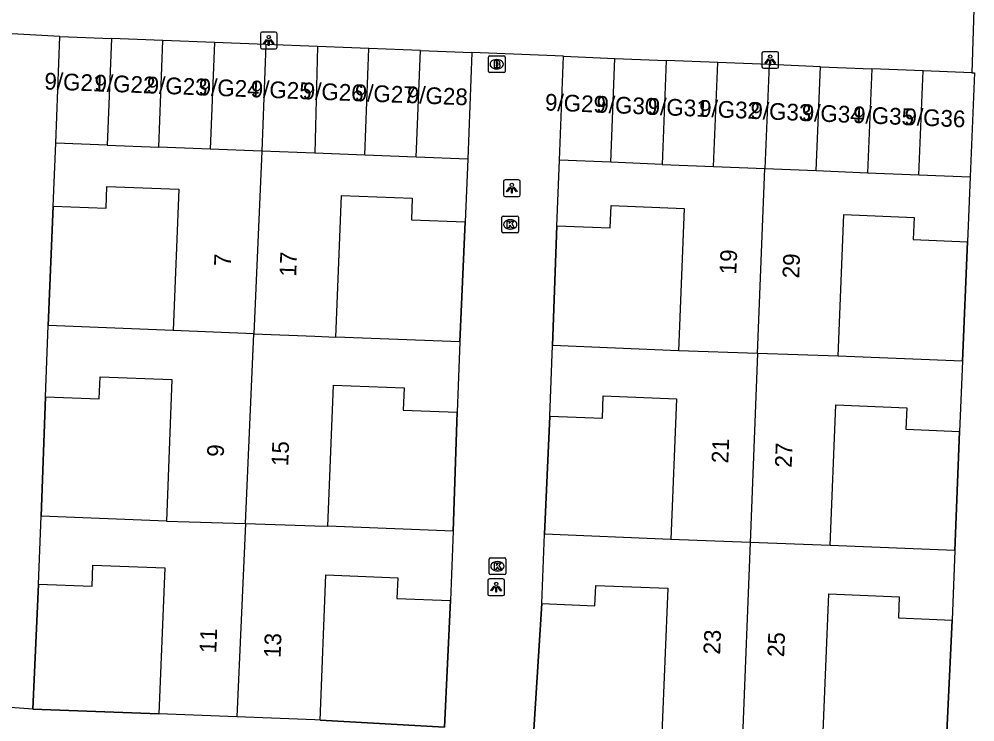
# Model space of a CAD drawing. Extents: x 160787 to 161428, y 386828 to 387483.
# Drawn here: x 160982.3 to 161039.5, y 387304.5 to 387346.5 of the extents above; entities that cross this region are included whole.
import ezdxf

# ---------------------------------------------------------------- set-up
doc = ezdxf.new("R2010")
doc.units = 0
for name, color, linetype in [('IMGEO_Brandkraan', 7, 'Continuous'), ('IMGEO_Kolk', 7, 'Continuous'), ('IMGEO_Lichtpunt', 7, 'Continuous'), ('IMGEO_Muur', 7, 'Continuous'), ('IMGEO_Pand', 7, 'Continuous'), ('IMGEO_Pand_nummerreeks', 7, 'Continuous'), ('IMGEO_Rijbaan_lokaal_open', 7, 'Continuous'), ('IMGEO_Voetpad_open', 7, 'Continuous')]:
    doc.layers.add(name, color=color, linetype=linetype)

msp = doc.modelspace()

# ---------------------------------------------------------------- linework, layer by layer
at = {"layer": 'IMGEO_Brandkraan'}
for p, q in [((161010.378, 387343.371), (161010.378, 387344.223)), ((161010.453, 387344.297), (161011.305, 387344.297)), ((161011.379, 387344.223), (161011.379, 387343.371)), ((161010.866, 387344.077), (161010.891, 387344.077)), ((161011.305, 387343.297), (161010.453, 387343.297)), ((161010.889, 387343.517), (161010.864, 387343.517))]:
    msp.add_line(p, q, dxfattribs=at)
for points in [[(161010.378, 387343.371), (161010.378, 387344.223)], [(161010.453, 387344.297), (161011.305, 387344.297)], [(161011.379, 387344.223), (161011.379, 387343.371)], [(161010.726, 387343.997), (161010.726, 387343.597), (161010.939, 387343.597)], [(161010.957, 387343.997), (161010.726, 387343.997)], [(161010.905, 387343.916), (161010.851, 387343.916), (161010.851, 387343.84)], [(161010.851, 387343.84), (161010.904, 387343.84)], [(161010.913, 387343.764), (161010.851, 387343.764), (161010.851, 387343.683)], [(161010.851, 387343.683), (161010.913, 387343.683)], [(161011.305, 387343.297), (161010.453, 387343.297)]]:
    msp.add_lwpolyline(points, dxfattribs=at)
for centre, radius, start, end in [((161010.455, 387344.221), 0.0765, 91.552, 178.448), ((161010.455, 387344.221), 0.0765, 91.552, 178.448), ((161011.303, 387344.221), 0.0765, 1.552, 88.448), ((161011.303, 387344.221), 0.0765, 1.552, 88.448), ((161010.906, 387343.878), 0.0379, 267.8285, 90.9355), ((161010.914, 387343.723), 0.0404, 269.8759, 90.5077), ((161010.945, 387343.848), 0.251, 268.6676, 293.5347), ((161010.961, 387343.852), 0.145, 59.4692, 91.5367), ((161010.986, 387343.899), 0.0922, 285.5137, 58.1501), ((161010.991, 387343.707), 0.105, 301.3115, 78.989), ((161010.455, 387343.373), 0.0765, 181.552, 268.448), ((161010.455, 387343.373), 0.0765, 181.552, 268.448), ((161011.303, 387343.373), 0.0765, 271.552, 358.448), ((161011.303, 387343.373), 0.0765, 271.552, 358.448)]:
    msp.add_arc(centre, radius, start, end, dxfattribs=at)
for centre, major_axis, ratio, start_param, end_param in [((161010.865, 387343.797), (-0.387, 0.002), 0.722429, 4.712389, 7.853982), ((161010.89, 387343.797), (-0.39, 0.002), 0.717154, 1.570796, 4.712389)]:
    msp.add_ellipse(centre, major_axis=major_axis, ratio=ratio, start_param=start_param, end_param=end_param, dxfattribs=at)
at = {"layer": 'IMGEO_Kolk'}
for p, q in [((161011.185, 387333.79), (161011.185, 387334.642)), ((161011.26, 387334.716), (161012.112, 387334.716)), ((161011.673, 387334.496), (161011.698, 387334.496)), ((161012.186, 387334.642), (161012.186, 387333.79)), ((161011.696, 387333.936), (161011.671, 387333.936)), ((161012.112, 387333.716), (161011.26, 387333.716)), ((161010.423, 387313.34), (161010.423, 387314.192)), ((161010.498, 387314.266), (161011.35, 387314.266)), ((161010.911, 387314.046), (161010.936, 387314.046)), ((161011.424, 387314.192), (161011.424, 387313.34)), ((161011.35, 387313.266), (161010.498, 387313.266)), ((161010.934, 387313.486), (161010.909, 387313.486))]:
    msp.add_line(p, q, dxfattribs=at)
for points in [[(161011.185, 387333.79), (161011.185, 387334.642)], [(161011.26, 387334.716), (161012.112, 387334.716)], [(161011.506, 387334.416), (161011.629, 387334.416), (161011.629, 387334.265), (161011.759, 387334.416), (161011.923, 387334.416), (161011.777, 387334.265), (161011.93, 387334.016), (161011.778, 387334.016), (161011.693, 387334.18), (161011.629, 387334.113), (161011.629, 387334.016), (161011.506, 387334.016), (161011.506, 387334.416)], [(161012.186, 387334.642), (161012.186, 387333.79)], [(161012.112, 387333.716), (161011.26, 387333.716)], [(161010.423, 387313.34), (161010.423, 387314.192)], [(161010.498, 387314.266), (161011.35, 387314.266)], [(161010.744, 387313.966), (161010.867, 387313.966), (161010.867, 387313.815), (161010.997, 387313.966), (161011.161, 387313.966), (161011.015, 387313.815), (161011.168, 387313.566), (161011.016, 387313.566), (161010.931, 387313.73), (161010.867, 387313.663), (161010.867, 387313.566), (161010.744, 387313.566), (161010.744, 387313.966)], [(161011.424, 387314.192), (161011.424, 387313.34)], [(161011.35, 387313.266), (161010.498, 387313.266)]]:
    msp.add_lwpolyline(points, dxfattribs=at)
for centre, start, end in [((161011.262, 387334.64), 91.552, 178.448), ((161011.262, 387334.64), 91.552, 178.448), ((161012.11, 387334.64), 1.552, 88.448), ((161012.11, 387334.64), 1.552, 88.448), ((161011.262, 387333.792), 181.552, 268.448), ((161011.262, 387333.792), 181.552, 268.448), ((161012.11, 387333.792), 271.552, 358.448), ((161012.11, 387333.792), 271.552, 358.448), ((161010.5, 387314.19), 91.552, 178.448), ((161010.5, 387314.19), 91.552, 178.448), ((161011.348, 387314.19), 1.552, 88.448), ((161011.348, 387314.19), 1.552, 88.448), ((161010.5, 387313.342), 181.552, 268.448), ((161010.5, 387313.342), 181.552, 268.448), ((161011.348, 387313.342), 271.552, 358.448), ((161011.348, 387313.342), 271.552, 358.448)]:
    msp.add_arc(centre, 0.0765, start, end, dxfattribs=at)
for centre, major_axis, ratio, start_param, end_param in [((161011.672, 387334.216), (-0.387, 0.002), 0.722429, 4.712389, 7.853982), ((161011.697, 387334.216), (-0.39, 0.002), 0.717154, 1.570796, 4.712389), ((161010.91, 387313.766), (-0.387, 0.002), 0.722429, 4.712389, 7.853982), ((161010.935, 387313.766), (-0.39, 0.002), 0.717154, 1.570796, 4.712389)]:
    msp.add_ellipse(centre, major_axis=major_axis, ratio=ratio, start_param=start_param, end_param=end_param, dxfattribs=at)
at = {"layer": 'IMGEO_Lichtpunt'}
for p, q in [((160996.743, 387345.622), (160996.743, 387344.815)), ((160996.743, 387345.622), (160996.743, 387344.815)), ((160997.645, 387345.717), (160996.837, 387345.717)), ((160997.645, 387345.717), (160996.837, 387345.717)), ((160997.739, 387344.815), (160997.739, 387345.622)), ((160997.739, 387344.815), (160997.739, 387345.622)), ((160996.837, 387344.721), (160997.645, 387344.721)), ((160996.837, 387344.721), (160997.645, 387344.721)), ((161026.739, 387344.454), (161026.739, 387343.647)), ((161026.739, 387344.454), (161026.739, 387343.647)), ((161027.641, 387344.549), (161026.833, 387344.549)), ((161027.641, 387344.549), (161026.833, 387344.549)), ((161027.735, 387343.647), (161027.735, 387344.454)), ((161027.735, 387343.647), (161027.735, 387344.454)), ((161026.833, 387343.553), (161027.641, 387343.553)), ((161026.833, 387343.553), (161027.641, 387343.553)), ((161011.284, 387336.783), (161011.284, 387335.976)), ((161011.284, 387336.783), (161011.284, 387335.976)), ((161012.186, 387336.878), (161011.378, 387336.878)), ((161012.186, 387336.878), (161011.378, 387336.878)), ((161012.28, 387335.976), (161012.28, 387336.783)), ((161012.28, 387335.976), (161012.28, 387336.783)), ((161011.378, 387335.882), (161012.186, 387335.882)), ((161011.378, 387335.882), (161012.186, 387335.882)), ((161010.348, 387312.914), (161010.348, 387312.107)), ((161010.348, 387312.914), (161010.348, 387312.107)), ((161011.25, 387313.009), (161010.442, 387313.009)), ((161011.25, 387313.009), (161010.442, 387313.009)), ((161011.344, 387312.107), (161011.344, 387312.914)), ((161011.344, 387312.107), (161011.344, 387312.914)), ((161010.442, 387312.013), (161011.25, 387312.013)), ((161010.442, 387312.013), (161011.25, 387312.013))]:
    msp.add_line(p, q, dxfattribs=at)
for points in [[(160997.117, 387345.286), (160997.156, 387345.258), (160996.968, 387344.996), (160996.93, 387345.023), (160997.117, 387345.286)], [(160997.329, 387345.258), (160997.367, 387345.285), (160997.554, 387345.023), (160997.515, 387344.995), (160997.329, 387345.258)], [(160997.219, 387345.238), (160997.266, 387345.238), (160997.266, 387344.916), (160997.219, 387344.916), (160997.219, 387345.238)], [(161027.113, 387344.118), (161027.152, 387344.09), (161026.964, 387343.828), (161026.926, 387343.855), (161027.113, 387344.118)], [(161027.325, 387344.09), (161027.363, 387344.117), (161027.55, 387343.855), (161027.511, 387343.827), (161027.325, 387344.09)], [(161027.215, 387344.07), (161027.262, 387344.07), (161027.262, 387343.748), (161027.215, 387343.748), (161027.215, 387344.07)], [(161011.658, 387336.447), (161011.697, 387336.419), (161011.509, 387336.157), (161011.471, 387336.184), (161011.658, 387336.447)], [(161011.76, 387336.399), (161011.807, 387336.399), (161011.807, 387336.077), (161011.76, 387336.077), (161011.76, 387336.399)], [(161011.87, 387336.419), (161011.908, 387336.446), (161012.095, 387336.184), (161012.056, 387336.156), (161011.87, 387336.419)], [(161010.722, 387312.578), (161010.761, 387312.55), (161010.573, 387312.288), (161010.535, 387312.315), (161010.722, 387312.578)], [(161010.824, 387312.53), (161010.871, 387312.53), (161010.871, 387312.208), (161010.824, 387312.208), (161010.824, 387312.53)], [(161010.934, 387312.55), (161010.972, 387312.577), (161011.159, 387312.315), (161011.12, 387312.287), (161010.934, 387312.55)]]:
    msp.add_lwpolyline(points, dxfattribs=at)
for centre in [(160997.242, 387345.42), (161027.238, 387344.252), (161011.783, 387336.581), (161010.847, 387312.712)]:
    msp.add_circle(centre, 0.0994, dxfattribs=at)
for centre, start, end in [((160996.837, 387345.622), 90, 180), ((160996.837, 387345.622), 90, 180), ((160997.645, 387345.622), 0, 90), ((160997.645, 387345.622), 0, 90), ((160996.837, 387344.815), 180, 270), ((160996.837, 387344.815), 180, 270), ((160997.645, 387344.815), 270, 0), ((160997.645, 387344.815), 270, 360), ((161026.833, 387344.454), 90, 180), ((161026.833, 387344.454), 90, 180), ((161027.641, 387344.454), 0, 90), ((161027.641, 387344.454), 0, 90), ((161026.833, 387343.647), 180, 270), ((161026.833, 387343.647), 180, 270), ((161027.641, 387343.647), 270, 0), ((161027.641, 387343.647), 270, 360), ((161011.378, 387336.783), 90, 180), ((161011.378, 387336.783), 90, 180), ((161012.186, 387336.783), 0, 90), ((161012.186, 387336.783), 0, 90), ((161011.378, 387335.976), 180, 270), ((161011.378, 387335.976), 180, 270), ((161012.186, 387335.976), 270, 0), ((161012.186, 387335.976), 270, 360), ((161010.442, 387312.914), 90, 180), ((161010.442, 387312.914), 90, 180), ((161011.25, 387312.914), 0, 90), ((161011.25, 387312.914), 0, 90), ((161010.442, 387312.107), 180, 270), ((161010.442, 387312.107), 180, 270), ((161011.25, 387312.107), 270, 0), ((161011.25, 387312.107), 270, 360)]:
    msp.add_arc(centre, 0.0946, start, end, dxfattribs=at)
at = {"layer": 'IMGEO_Muur'}
for points in [[(160984.36, 387335.313), (160984.055, 387328.17)], [(161008.672, 387327.188), (161008.998, 387334.368)], [(161014.47, 387334.14), (161014.22, 387326.967)], [(161038.733, 387326.037), (161039.04, 387333.18)], [(160983.887, 387323.905), (160983.626, 387316.762)], [(161008.28, 387315.875), (161008.507, 387322.987)], [(161014.049, 387322.75), (161013.745, 387315.68)], [(161038.281, 387314.709), (161038.563, 387321.838)], [(160983.467, 387312.699), (160983.144, 387305.21), (160990.678, 387304.943)], [(161000.326, 387304.564), (161007.761, 387304.145), (161008.117, 387311.71)], [(161013.577, 387311.533), (161013.104, 387303.992)], [(161037.77, 387302.999), (161038.112, 387310.547)]]:
    msp.add_lwpolyline(points, dxfattribs=at)
at = {"layer": 'IMGEO_Pand'}
for points in [[(160984.508, 387339.08), (160984.758, 387345.458)], [(160984.758, 387345.458), (160987.838, 387345.337)], [(160987.838, 387345.337), (160987.587, 387338.959)], [(160990.918, 387345.216), (160987.838, 387345.337)], [(160990.667, 387338.837), (160990.918, 387345.216)], [(160993.997, 387345.095), (160990.918, 387345.216)], [(160993.997, 387345.095), (160993.747, 387338.716)], [(160997.077, 387344.975), (160993.997, 387345.095)], [(160997.077, 387344.975), (160996.826, 387338.595)], [(161000.157, 387344.854), (160997.077, 387344.975)], [(161000.157, 387344.854), (161000, 387338.47)], [(161003.236, 387344.733), (161000.157, 387344.854)], [(161002.986, 387338.352), (161003.236, 387344.733)], [(161006.316, 387344.612), (161003.236, 387344.733)], [(161006.066, 387338.231), (161006.316, 387344.612)], [(161006.316, 387344.612), (161009.396, 387344.491)], [(161009.396, 387344.491), (161009.145, 387338.11)], [(161014.629, 387338.054), (161014.881, 387344.271)], [(161014.881, 387344.271), (161017.952, 387344.147)], [(161017.7, 387337.93), (161017.952, 387344.147)], [(161017.952, 387344.147), (161021.023, 387344.022)], [(161021.023, 387344.022), (161020.771, 387337.805)], [(161024.094, 387343.898), (161021.023, 387344.022)], [(161023.842, 387337.681), (161024.094, 387343.898)], [(161027.165, 387343.773), (161024.094, 387343.898)], [(161027.165, 387343.773), (161026.913, 387337.556)], [(161030.236, 387343.648), (161027.165, 387343.773)], [(161029.984, 387337.432), (161030.236, 387343.648)], [(161030.236, 387343.648), (161033.307, 387343.524)], [(161033.307, 387343.524), (161033.055, 387337.308)], [(161036.378, 387343.4), (161033.307, 387343.524)], [(161036.126, 387337.183), (161036.378, 387343.4)], [(161039.295, 387343.281), (161036.378, 387343.4)], [(161039.295, 387343.281), (161039.449, 387343.275), (161039.197, 387337.059)], [(160984.36, 387335.313), (160984.508, 387339.08)], [(160987.587, 387338.959), (160984.508, 387339.08)], [(160987.587, 387338.959), (160990.667, 387338.837)], [(160993.747, 387338.716), (160990.667, 387338.837)], [(160996.826, 387338.595), (160993.747, 387338.716)], [(160996.826, 387338.595), (160996.347, 387327.679)], [(161000, 387338.47), (160996.826, 387338.595)], [(161002.986, 387338.352), (161000, 387338.47)], [(161006.066, 387338.231), (161002.986, 387338.352)], [(161009.145, 387338.11), (161006.066, 387338.231)], [(161009.145, 387338.11), (161008.998, 387334.368)], [(161014.47, 387334.14), (161014.629, 387338.054)], [(161017.7, 387337.93), (161014.629, 387338.054)], [(161020.771, 387337.805), (161017.7, 387337.93)], [(161020.771, 387337.805), (161023.842, 387337.681)], [(161023.842, 387337.681), (161026.913, 387337.556)], [(161026.481, 387326.501), (161026.913, 387337.556)], [(161026.913, 387337.556), (161029.984, 387337.432)], [(161029.984, 387337.432), (161033.055, 387337.308)], [(161033.055, 387337.308), (161036.126, 387337.183)], [(161036.126, 387337.183), (161039.197, 387337.059)], [(161039.197, 387337.059), (161039.04, 387333.18)], [(160984.36, 387335.313), (160987.515, 387335.189), (160987.566, 387336.487), (160991.867, 387336.318), (160991.535, 387327.877)], [(161001.261, 387327.479), (161001.594, 387335.945), (161005.83, 387335.779), (161005.779, 387334.495), (161008.998, 387334.368)], [(161014.47, 387334.14), (161017.671, 387334.01), (161017.725, 387335.344), (161022.092, 387335.167), (161021.747, 387326.662)], [(161031.293, 387326.339), (161031.637, 387334.808), (161035.85, 387334.637), (161035.796, 387333.312), (161039.04, 387333.18)], [(160983.887, 387323.905), (160984.055, 387328.17)], [(160991.535, 387327.877), (160984.055, 387328.17)], [(160996.347, 387327.679), (160991.535, 387327.877)], [(160995.848, 387316.323), (160996.347, 387327.679)], [(160996.347, 387327.679), (161000, 387327.531), (161001.261, 387327.479)], [(161008.672, 387327.188), (161001.261, 387327.479)], [(161008.672, 387327.188), (161008.507, 387322.987)], [(161014.049, 387322.75), (161014.22, 387326.967)], [(161021.747, 387326.662), (161014.22, 387326.967)], [(161026.481, 387326.501), (161021.747, 387326.662)], [(161026.481, 387326.501), (161026.033, 387315.194)], [(161031.293, 387326.339), (161026.481, 387326.501)], [(161038.733, 387326.037), (161031.293, 387326.339)], [(161038.733, 387326.037), (161038.563, 387321.838)], [(160983.887, 387323.905), (160987.102, 387323.779), (160987.153, 387325.1), (160991.451, 387324.932), (160991.119, 387316.47)], [(161000.786, 387316.169), (161001.117, 387324.596), (161005.345, 387324.431), (161005.293, 387323.113), (161008.507, 387322.987)], [(161014.049, 387322.75), (161017.2, 387322.622), (161017.254, 387323.955), (161021.639, 387323.778), (161021.298, 387315.375)], [(161030.823, 387315.011), (161031.163, 387323.417), (161035.409, 387323.245), (161035.357, 387321.968), (161038.563, 387321.838)], [(160983.467, 387312.699), (160983.626, 387316.762)], [(160991.119, 387316.47), (160983.626, 387316.762)], [(160991.119, 387316.47), (160995.848, 387316.323)], [(160995.848, 387316.323), (160995.34, 387304.76)], [(160995.848, 387316.323), (161000, 387316.194), (161000.786, 387316.169)], [(161008.28, 387315.875), (161000.786, 387316.169)], [(161008.28, 387315.875), (161008.117, 387311.71)], [(161013.577, 387311.533), (161013.745, 387315.68)], [(161021.298, 387315.375), (161013.745, 387315.68)], [(161026.033, 387315.194), (161021.298, 387315.375)], [(161026.033, 387315.194), (161025.572, 387303.577)], [(161030.823, 387315.011), (161026.033, 387315.194)], [(161038.281, 387314.709), (161030.823, 387315.011)], [(161038.281, 387314.709), (161038.112, 387310.547)], [(160983.467, 387312.699), (160986.677, 387312.573), (160986.727, 387313.842), (160991.02, 387313.673), (160990.678, 387304.943)], [(161000.326, 387304.564), (161000.667, 387313.245), (161004.96, 387313.077), (161004.912, 387311.836), (161008.117, 387311.71)], [(161013.577, 387311.533), (161016.756, 387311.404), (161016.805, 387312.626), (161021.106, 387312.451), (161020.754, 387303.772)], [(161030.392, 387303.382), (161030.746, 387312.109), (161034.957, 387311.939), (161034.906, 387310.676), (161038.112, 387310.547)], [(160995.34, 387304.76), (160990.678, 387304.943)], [(161000.326, 387304.564), (161000, 387304.577), (160995.34, 387304.76)]]:
    msp.add_lwpolyline(points, dxfattribs=at)
at = {"layer": 'IMGEO_Rijbaan_lokaal_open'}
for points in [[(161039.478, 387348.98), (161039.295, 387343.281)], [(160984.758, 387345.458), (160979.333, 387345.754)], [(161014.881, 387344.271), (161009.396, 387344.491)]]:
    msp.add_lwpolyline(points, dxfattribs=at)
at = {"layer": 'IMGEO_Voetpad_open'}
for points in [[(160984.055, 387328.17), (160984.36, 387335.313)], [(161008.998, 387334.368), (161008.672, 387327.188)], [(161014.22, 387326.967), (161014.47, 387334.14)], [(161039.04, 387333.18), (161038.733, 387326.037)], [(160983.626, 387316.762), (160983.887, 387323.905)], [(161008.507, 387322.987), (161008.28, 387315.875)], [(161013.745, 387315.68), (161014.049, 387322.75)], [(161038.563, 387321.838), (161038.281, 387314.709)], [(160983.144, 387305.21), (160983.467, 387312.699)], [(161008.117, 387311.71), (161007.761, 387304.145)], [(161013.104, 387303.992), (161013.577, 387311.533)], [(161038.112, 387310.547), (161037.77, 387302.999)], [(160983.144, 387305.21), (160977.765, 387305.618)], [(160990.678, 387304.943), (160983.144, 387305.21)], [(161007.761, 387304.145), (161000.326, 387304.564)]]:
    msp.add_lwpolyline(points, dxfattribs=at)

# ---------------------------------------------------------------- texts
at = {"layer": 'IMGEO_Pand_nummerreeks'}
for s, rotation, p in [('9/G21', 357.8434, (160983.812, 387342.292)), ('9/G22', 357.8434, (160986.808, 387342.179)), ('9/G23', 357.8434, (160989.926, 387342.061)), ('9/G24', 357.8434, (160993.038, 387341.944)), ('9/G25', 357.8434, (160996.15, 387341.827)), ('9/G26', 357.8434, (160999.262, 387341.71)), ('9/G27', 357.8434, (161002.374, 387341.593)), ('9/G28', 357.8434, (161005.489, 387341.475)), ('9/G29', 357.6785, (161013.752, 387341.034)), ('9/G30', 357.6785, (161016.823, 387340.91)), ('9/G31', 357.6785, (161019.894, 387340.785)), ('9/G32', 357.6785, (161022.965, 387340.661)), ('9/G33', 357.6785, (161026.036, 387340.536)), ('9/G34', 357.6785, (161029.107, 387340.412)), ('9/G35', 357.6785, (161032.178, 387340.287)), ('9/G36', 357.6795, (161035.249, 387340.163)), ('7', 87.7476, (160994.968, 387331.694)), ('17', 87.7475, (160998.881, 387331.077)), ('19', 87.5686, (161025.203, 387331.211)), ('29', 87.727, (161028.965, 387330.973)), ('21', 87.5686, (161024.723, 387319.908)), ('9', 87.7537, (160994.552, 387320.296)), ('15', 87.7507, (160998.405, 387319.747)), ('27', 87.727, (161028.516, 387319.647)), ('11', 87.7566, (160994.103, 387308.559)), ('23', 87.5686, (161024.237, 387308.47)), ('13', 87.7505, (160997.95, 387308.269)), ('25', 87.727, (161028.066, 387308.32))]:
    msp.add_text(s, height=1, rotation=rotation, dxfattribs=at).set_placement(p)

doc.saveas('drawing.dxf')
